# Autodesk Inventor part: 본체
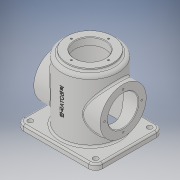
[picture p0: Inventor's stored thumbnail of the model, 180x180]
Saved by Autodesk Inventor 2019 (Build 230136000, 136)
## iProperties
Created: 2020-12
Part Number: 본체
Material: 일반
Document SubType Name: Modeling
Designer: jun-1-10
Density: 1 g/cm^3
Appearance: 기본값
Mass: 457.576 g
Surface Area: 1067.12 cm^2
Volume: 457.576 cm^3
Author: jun-1-10
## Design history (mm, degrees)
sketch "스케치1"
  geometry: L1 (70, 60)-(-70, 60); L2 (-70, 60)-(-70, -60); L3 (-70, -60)-(70, -60); L4 (70, -60)-(70, 60); L5 (70, 60)-(-70, -60); L6 (-70, 60)-(70, -60); 1 further point
  constraints: 12 end point, 2 midpoint, 2 parallel, 1 horizontal, 1 perpendicular
  dimensions: "d0" = 140 distance of L3.end L2.end; "d1" = 120 distance of L2.end L1.end
extrude "돌출1" new body sketch "스케치1" distance "d2" = 10; taper "d3" = 0 deg
sketch "스케치2"
  geometry: C1 r 50 at (0, 0); 1 further point
  constraints: 1 centre point, 1 coincident
  dimensions: "d4" = 100 diameter of C1
extrude "돌출2" join sketch "스케치2" distance "d5" = 110; taper "d6" = 0 deg; dims "d21" = 112
sketch "스케치3"
  geometry: C1 r 50 at (0, 0) reference; 2 further points
  constraints: 1 coincident
hole "구멍1" sketch "스케치3" at (0, 0) diameter "d7" = 54; stored, may be unused: countersink angle "d11" = 90 deg, drill point angle "d13" = 118 deg; dims "d8" = 6, "d9" = 84, "d10" = 112, "d12" = 8
node "작업 평면2"
sketch "스케치5"
  geometry: L1 (0, 60)-(0, -60) reference; C1 r 41 at (60, 0); 2 further points
  constraints: 1 centre point, 1 horizontal alignment, 1 midpoint
  dimensions: "d15" = 82 diameter of C1; "d69" = 60 distance from line of L1 C1.centre
extrude "돌출3" join sketch "스케치5" stored distance "d16" = 110; taper "d17" = 0 deg
sketch "스케치6"
  geometry: C1 r 41 at (0, 0) reference; 2 further points
  constraints: 1 coincident
hole "구멍2" sketch "스케치6" at (0, 0) diameter "d18" = 54; stored, may be unused: countersink angle "d22" = 90 deg, drill point angle "d24" = 118 deg; dims "d19" = 6, "d20" = 84, "d21" = 112, "d23" = 8
sketch "스케치7" dims "d25" = 66
  geometry: C1 r 41 at (0, 0) reference; 3 further points
  constraints: 2 vertical alignment, 1 coincident, 2 other
hole "구멍3" sketch "스케치7" at (0, 33) diameter "d26" = 3.242; stored, may be unused: countersink angle "d30" = 90 deg, drill point angle "d32" = 118 deg; dims "d27" = 8, "d28" = 84, "d29" = 112, "d31" = 10
sketch "스케치8"
  geometry: C1 r 41 at (0, 0); C2 r 27 at (0, 0) reference; 1 further point
  constraints: 1 centre point, 1 coincident
  dimensions: "d36" = 82 diameter of C1
extrude "돌출4" join sketch "스케치8" distance "d37" = 5; taper "d38" = 0 deg
sketch "스케치9" dims "d39" = 66
  geometry: 3 further points
  constraints: 2 vertical alignment, 1 coincident, 2 other
hole "구멍4" sketch "스케치9" at (0, 33) diameter "d40" = 3.242; stored, may be unused: countersink angle "d44" = 90 deg, drill point angle "d46" = 118 deg; dims "d41" = 8, "d42" = 84, "d43" = 112, "d45" = 10
fillet "모깎기1" dims "d50" = 6
fillet "모깎기2" dims "d51" = 12
fillet "모깎기3" dims "d52" = 3
fillet "모깎기4" dims "d53" = 3
fillet "모깎기5" dims "d54" = 3
fillet "모깎기6" dims "d55" = 3
chamfer "모따기1" distance "d56" = 1; stored, may be unused: second distance "d57" = 2, angle "d58" = 45 deg
chamfer "모따기2" distance "d59" = 1; stored, may be unused: second distance "d60" = 2, angle "d61" = 45 deg
fillet "모깎기7" dims "d70" = 3
sketch "스케치11"
  geometry: A1 r 9 centre (-58, -48) between (-67, -48) and (-58, -57) reference; 2 further points
  constraints: 1 coincident
hole "구멍6" sketch "스케치11" at (-58, -48) diameter "d71" = 9; stored, may be unused: countersink angle "d75" = 90 deg, drill point angle "d77" = 118 deg; dims "d72" = 8, "d73" = 84, "d74" = 112, "d76" = 10
sketch "스케치12"
  geometry: A1 r 9 centre (58, -48) between (58, -57) and (67, -48) reference; 2 further points
  constraints: 1 coincident
hole "구멍7" sketch "스케치12" at (58, -48) diameter "d78" = 9; stored, may be unused: countersink angle "d82" = 90 deg, drill point angle "d84" = 118 deg; dims "d79" = 8, "d80" = 84, "d81" = 112, "d83" = 10
sketch "스케치13"
  geometry: A1 r 9 centre (-58, 48) between (-58, 57) and (-67, 48) reference; 2 further points
  constraints: 1 coincident
hole "구멍8" sketch "스케치13" at (-58, 48) diameter "d85" = 9; stored, may be unused: countersink angle "d89" = 90 deg, drill point angle "d91" = 118 deg; dims "d86" = 8, "d87" = 84, "d88" = 112, "d90" = 10
sketch "스케치14"
  geometry: A1 r 9 centre (58, 48) between (67, 48) and (58, 57) reference; 2 further points
  constraints: 1 coincident
hole "구멍9" sketch "스케치14" at (58, 48) diameter "d92" = 9; stored, may be unused: countersink angle "d96" = 90 deg, drill point angle "d98" = 118 deg; dims "d93" = 8, "d94" = 84, "d95" = 112, "d97" = 10
node "작업 평면3"
sketch "스케치15"
  geometry: L1 (-58, -10)-(58, -10) reference; 3 further points
  constraints: 1 midpoint, 1 vertical alignment, 1 other
  dimensions: "d99" = 70 distance from line of L1 point (0, 60)
feature "엠보싱1" sketch "스케치15" dims "d0" = 140, "d1" = 120, "d15" = 82, "d69" = 60, "d100" = 0.5, "d101" = 0
node "솔리드1"
mirror "미러1"
pattern_circular "원형 패턴1" dims angle "d34" = 360 deg
mirror "미러2"
pattern_circular "원형 패턴2" dims angle "d48" = 360 deg
other parameters: "d14" = 59
